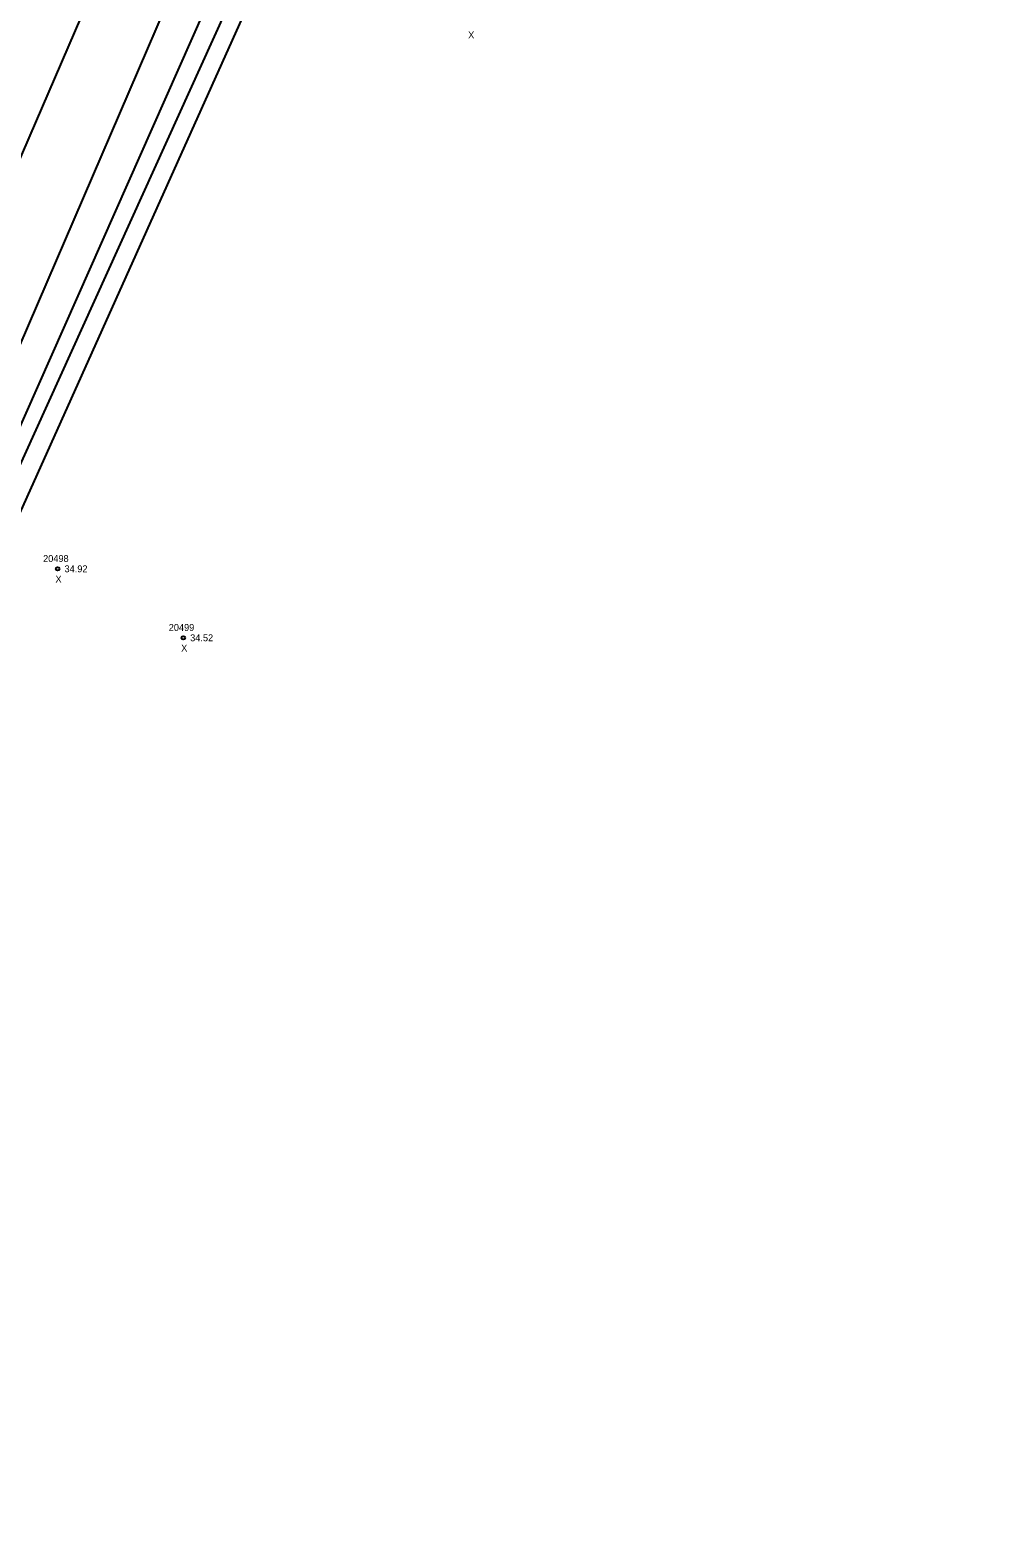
# Model space of a CAD drawing. Extents: x 2432729 to 2433340, y 684958 to 688103.
# Drawn here: x 2432960.9 to 2433102.1, y 685196.9 to 685416.3 of the extents above; entities that cross this region are included whole.
import ezdxf

# ---------------------------------------------------------------- set-up
doc = ezdxf.new("R2010")
doc.units = 0
for name, color, linetype in [('RD_DTM_BkLn1', 7, 'Continuous'), ('RD_EX_H2O', 7, 'Continuous'), ('RD_EX_Road', 7, 'Continuous'), ('RD_Sketch8', 7, 'Continuous'), ('RD_SMD_Locator', 7, 'Continuous')]:
    doc.layers.add(name, color=color, linetype=linetype)

msp = doc.modelspace()

# ---------------------------------------------------------------- linework, layer by layer
at = {"layer": 'RD_DTM_BkLn1'}
for points in [[(2433067.41, 685690.62), (2433052.49, 685638.4), (2433035.04, 685585.7), (2433018.41, 685541.16), (2432999.85, 685493.3), (2432978.77, 685442.62), (2432938.71, 685349.86), (2432898.27, 685257.39), (2432861.69, 685174.74), (2432859.51, 685169.85), (2432818.13, 685076.09), (2432777.09, 684983.43)], [(2433087.86, 685684.95), (2433070.24, 685632.97), (2433050.83, 685581.32), (2433032.43, 685535.6), (2433015.06, 685486.22), (2432993.56, 685435.75), (2432952.83, 685343.93), (2432911.02, 685251.28), (2432891.52, 685205.36), (2432897.43, 685203.55)], [(2433102.05, 685679.62), (2433079.53, 685630.77), (2433059.07, 685578.75), (2433039.78, 685531.36), (2433020.13, 685482.85), (2432998.25, 685432.63), (2432957.4, 685341.66), (2432916.69, 685248.39), (2432897.43, 685203.55)]]:
    msp.add_lwpolyline(points, dxfattribs=at)
at = {"layer": 'RD_EX_H2O'}
msp.add_lwpolyline([(2433091.72, 685683.25), (2433072.97, 685632.18), (2433053.46, 685580.43), (2433036.38, 685533.4), (2433017.44, 685484.85), (2432996.16, 685434.2), (2432954.84, 685343.07), (2432912.85, 685250.04), (2432894.77, 685206.8)], dxfattribs=at)
at = {"layer": 'RD_EX_Road'}
msp.add_lwpolyline([(2433077.66, 685687.92), (2433062.23, 685635.7), (2433044.84, 685582.68), (2433028.22, 685537.07), (2433009.68, 685489.83), (2432988.53, 685438.27), (2432948.62, 685345.62), (2432907.86, 685252.74), (2432887.37, 685205.96), (2432872.08, 685170.45), (2432827.85, 685071.69), (2432787.31, 684979.59)], dxfattribs=at)
at = {"layer": 'RD_SMD_Locator'}
for centre in [(2432964.89, 685337.93), (2432983.18, 685327.89)]:
    msp.add_circle(centre, 0.25, dxfattribs=at)

# ---------------------------------------------------------------- texts
at = {"layer": 'RD_Sketch8'}
for s, p in [('X', (2433024.65, 685415.15)), ('20498', (2432962.77, 685338.93)), ('X', (2432964.57, 685335.93)), ('34.92', (2432965.89, 685337.43)), ('20499', (2432981.06, 685328.89)), ('34.52', (2432984.18, 685327.39)), ('X', (2432982.87, 685325.89))]:
    msp.add_text(s, height=1, dxfattribs=at).set_placement(p)

doc.saveas('drawing.dxf')
